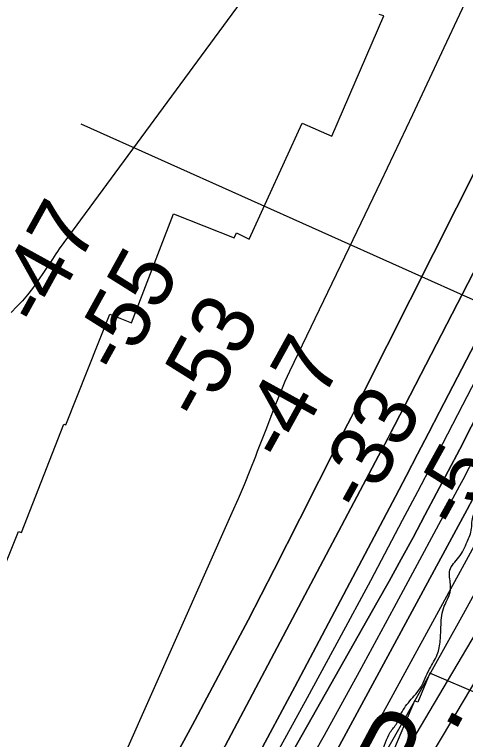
# Model space of a CAD drawing. Extents: x 3297735 to 3335592, y 670436 to 695807.
# Drawn here: x 3321993 to 3322478, y 692965 to 693745 of the extents above; entities that cross this region are included whole.
import ezdxf

# ---------------------------------------------------------------- set-up
doc = ezdxf.new("R2010")
doc.units = 0
for name, color, linetype in [('V-RIVR-EDGE', 7, 'Continuous'), ('V-RIVR-RANG', 7, 'Continuous'), ('V-RRAP-RVMT', 7, 'Continuous'), ('V-TOPO-DPTH', 7, 'Continuous'), ('V-TOPO-MAJR', 7, 'Continuous'), ('V-TOPO-MINR', 7, 'Continuous'), ('V-TOPO-WATR', 7, 'Continuous'), ('V-TOPO-WATR-IDEN', 7, 'Continuous')]:
    doc.layers.add(name, color=color, linetype=linetype)

msp = doc.modelspace()

# ---------------------------------------------------------------- linework, layer by layer
at = {"layer": 'V-RIVR-EDGE'}
msp.add_spline([(3319721.91, 688607.25), (3319733.2, 688627.78), (3319739.82, 688637.46), (3319746.04, 688644.42), (3319750.72, 688655.27), (3319752.28, 688659.14), (3319762.01, 688671.92), (3319781.47, 688699.79), (3319792.76, 688716.44), (3319801.32, 688726.89), (3319810.26, 688738.11), (3319819.98, 688747.01), (3319825.43, 688754.75), (3319830.49, 688762.88), (3319835.55, 688770.63), (3319840.23, 688780.31), (3319844.52, 688791.16), (3319846.86, 688795.42), (3319851.13, 688797.35), (3319854.24, 688799.66), (3319861.24, 688808.95), (3319869.41, 688820.96), (3319874.87, 688831.03), (3319884.99, 688845.35), (3319893.93, 688856.57), (3319900.54, 688860.82), (3319908.31, 688869.72), (3319918.43, 688881.33), (3319923.49, 688889.46), (3319928.16, 688897.21), (3319932.06, 688904.95), (3319939.44, 688912.69), (3319951.5, 688924.3), (3319955, 688930.88), (3319970.57, 688952.17), (3319976.4, 688958.36), (3319980.68, 688966.5), (3319987.3, 688976.95), (3319991.2, 688986.25), (3319997.81, 688992.82), (3320004.81, 689000.56), (3320006.38, 689006.76), (3320010.27, 689012.96), (3320018.06, 689024.96), (3320025.07, 689035.8), (3320031.68, 689044.71), (3320039.46, 689054.38), (3320044.52, 689060.57), (3320057.73, 689071.4), (3320064.34, 689077.2), (3320070.17, 689082.23), (3320074.45, 689090.36), (3320085.73, 689104.68), (3320093.52, 689116.3), (3320109.84, 689130.22), (3320125, 689144.14), (3320145.59, 689159.99), (3320166.96, 689177), (3320184.06, 689191.31), (3320194.55, 689197.87), (3320205.42, 689204.44), (3320211.64, 689209.85), (3320219.42, 689219.53), (3320234.59, 689238.11), (3320241.98, 689244.68), (3320253.64, 689257.45), (3320273.09, 689279.5), (3320283.99, 689297.32), (3320297.61, 689318.61), (3320312.03, 689344.56), (3320320.21, 689360.83), (3320328.41, 689380.97), (3320333.48, 689394.53), (3320349.85, 689425.9), (3320363.1, 689453.41), (3320368.17, 689465.42), (3320370.9, 689469.67), (3320379.06, 689477.41), (3320388.4, 689489.8), (3320394.62, 689499.09), (3320395.41, 689505.29), (3320397.76, 689513.82), (3320403.21, 689520.78), (3320409.04, 689527.75), (3320417.6, 689536.65), (3320423.43, 689544.39), (3320428.49, 689552.52), (3320431.24, 689564.54), (3320432.02, 689568.03), (3320442.14, 689581.19), (3320451.87, 689595.12), (3320462.77, 689612.93), (3320469.38, 689621.06), (3320477.55, 689631.51), (3320493.51, 689653.19), (3320500.9, 689665.19), (3320506.36, 689674.1), (3320514.54, 689688.82), (3320523.5, 689705.47), (3320534.4, 689723.28), (3320539.06, 689727.15), (3320544.9, 689735.28), (3320551.13, 689744.18), (3320556.58, 689752.7), (3320560.87, 689764.32), (3320568.26, 689774), (3320574.5, 689785.23), (3320578.79, 689794.53), (3320583.07, 689802.27), (3320590.86, 689815.83), (3320602.92, 689833.25), (3320613.43, 689849.12), (3320622.79, 689866.94), (3320636.42, 689890.17), (3320646.93, 689907.21), (3320658.22, 689926.96), (3320664.85, 689940.13), (3320664.87, 689948.66), (3320667.22, 689956.02), (3320676.55, 689968.02), (3320685.11, 689978.08), (3320691.73, 689991.25), (3320701.47, 690006.35), (3320706.14, 690016.04), (3320709.66, 690026.11), (3320715.89, 690035.79), (3320728.33, 690049.33), (3320741.18, 690068.69), (3320754.02, 690086.5), (3320761.81, 690100.44), (3320770.77, 690116.32), (3320777.39, 690127.16), (3320786.73, 690139.93), (3320794.89, 690149.22), (3320800.73, 690155.41), (3320806.18, 690166.26), (3320810.47, 690174), (3320820.98, 690192.59), (3320823.74, 690207.71), (3320829.97, 690218.16), (3320840.87, 690235.59), (3320854.1, 690256.5), (3320864.22, 690271.59), (3320869.28, 690277.01), (3320870.45, 690281.27), (3320876.68, 690289.4), (3320887.57, 690302.95), (3320901.57, 690319.98), (3320912.08, 690333.52), (3320919.47, 690342.43), (3320924.52, 690348.23), (3320932.3, 690356.35), (3320941.26, 690371.46), (3320956.44, 690393.91), (3320969.67, 690415.21), (3320973.57, 690422.57), (3320982.13, 690434.96), (3320987.2, 690444.64), (3320994.21, 690457.03), (3321000.83, 690467.87), (3321008.23, 690481.04), (3321017.97, 690500.02), (3321024.59, 690511.64), (3321030.43, 690518.6), (3321035.5, 690530.22), (3321040.94, 690537.19), (3321055.35, 690559.26), (3321068.58, 690577.84), (3321078.31, 690594.1), (3321086.87, 690605.72), (3321095.82, 690616.94), (3321102.82, 690625.84), (3321107.51, 690637.85), (3321113.34, 690645.6), (3321117.63, 690655.67), (3321123.87, 690670), (3321130.5, 690682.39), (3321142.57, 690701.37), (3321156.19, 690722.28), (3321168.65, 690743.19), (3321171.38, 690749.38), (3321176.05, 690754.41), (3321177.22, 690758.29), (3321181.12, 690767.2), (3321185.79, 690774.17), (3321192.03, 690789.28), (3321204.89, 690814.45), (3321214.25, 690834.98), (3321218.93, 690845.83), (3321223.61, 690855.12), (3321229.85, 690869.85), (3321238.03, 690883.79), (3321242.33, 690899.29), (3321247.41, 690912.46), (3321254.43, 690927.96), (3321263, 690946.55), (3321269.64, 690962.82), (3321273.93, 690973.67), (3321278.23, 690986.07), (3321286.44, 691015.52), (3321288.78, 691021.72), (3321293.84, 691028.3), (3321297.35, 691034.5), (3321303.19, 691045.34), (3321306.32, 691054.64), (3321308.29, 691066.66), (3321310.63, 691073.63), (3321314.52, 691079.44), (3321318.04, 691090.29), (3321320.01, 691103.08), (3321324.31, 691115.87), (3321326.26, 691120.13), (3321332.09, 691125.16), (3321336.76, 691133.68), (3321337.17, 691140.65), (3321337.18, 691146.47), (3321338.37, 691158.49), (3321341.12, 691172.44), (3321349.71, 691192.98), (3321372.69, 691236.35), (3321389.06, 691268.5), (3321398.41, 691284.38), (3321404.65, 691298.32), (3321407.38, 691307.24), (3321407.39, 691310.73), (3321407.79, 691316.15), (3321414.41, 691325.06), (3321416.76, 691334.75), (3321417.94, 691344.05), (3321422.24, 691356.06), (3321434.34, 691385.89), (3321448.39, 691422.7), (3321456.19, 691442.46), (3321462.05, 691458.34), (3321462.85, 691466.87), (3321467.91, 691477.72), (3321474.92, 691488.17), (3321481.15, 691497.85), (3321481.54, 691500.57), (3321489.74, 691519.94), (3321499.87, 691542.02), (3321510.79, 691564.87), (3321521.69, 691581.91), (3321529.1, 691598.18), (3321538.84, 691619.09), (3321550.12, 691632.64), (3321559.06, 691640.76), (3321566.84, 691650.44), (3321566.47, 691655.48), (3321567.25, 691659.74), (3321572.7, 691664.77), (3321581.26, 691676.38), (3321584.38, 691684.91), (3321587.11, 691693.43), (3321593.35, 691706.6), (3321601.92, 691721.7), (3321610.87, 691733.32), (3321617.87, 691739.5), (3321620.99, 691748.8), (3321624.5, 691755), (3321632.28, 691766.23), (3321637.34, 691773.97), (3321638.14, 691784.44), (3321641.66, 691795.29), (3321645.96, 691809.63), (3321651.03, 691820.47), (3321653.37, 691824.35), (3321658.42, 691828.99), (3321665.02, 691832.07), (3321673.18, 691838.64), (3321680.2, 691853.75), (3321683.72, 691866.15), (3321687.24, 691878.94), (3321691.93, 691892.5), (3321697.77, 691904.12), (3321704.38, 691909.54), (3321711, 691920.77), (3321724.23, 691939.74), (3321729.68, 691949.8), (3321733.59, 691959.49), (3321746.04, 691978.85), (3321765.1, 692000.13), (3321767.83, 692005.55), (3321769.01, 692012.53), (3321772.52, 692019.89), (3321782.64, 692034.6), (3321793.52, 692045.43), (3321802.86, 692057.43), (3321811.04, 692071.76), (3321820.77, 692085.31), (3321837.5, 692109.31), (3321852.67, 692125.56), (3321856.95, 692134.47), (3321865.51, 692146.08), (3321874.07, 692158.09), (3321882.62, 692162.33), (3321885.73, 692165.42), (3321887.31, 692179.77), (3321889.66, 692189.46), (3321896.67, 692199.14), (3321906.39, 692208.81), (3321914.56, 692218.87), (3321921.95, 692230.87), (3321931.31, 692249.47), (3321940.25, 692259.91), (3321951.52, 692266.48), (3321951.14, 692271.52), (3321953.48, 692276.17), (3321960.48, 692283.13), (3321960.49, 692288.17), (3321960.5, 692292.05), (3321966.73, 692300.96), (3321976.84, 692312.95), (3321985.4, 692326.12), (3321999.02, 692342.37), (3322004.07, 692347.79), (3322006.8, 692355.15), (3322018.86, 692369.86), (3322032.48, 692387.27), (3322035.98, 692394.25), (3322046.88, 692410.89), (3322053.89, 692419.41), (3322062.45, 692431.8), (3322080.36, 692459.29), (3322099.43, 692486.77), (3322109.15, 692500.71), (3322113.45, 692513.5), (3322120.08, 692527.44), (3322124.37, 692536.35), (3322130.59, 692544.09), (3322144.19, 692555.69), (3322154.3, 692563.42), (3322157.8, 692568.07), (3322157.81, 692573.5), (3322158.99, 692580.09), (3322165.23, 692595.2), (3322169.9, 692601), (3322176.9, 692609.9), (3322181.58, 692618.04), (3322185.48, 692627.33), (3322187.82, 692635.08), (3322190.16, 692638.96), (3322199.11, 692652.12), (3322206.11, 692660.24), (3322215.05, 692669.14), (3322221.67, 692679.21), (3322228.68, 692689.66), (3322230.65, 692701.29), (3322234.15, 692707.1), (3322239.98, 692713.68), (3322240.78, 692721.82), (3322246.62, 692732.28), (3322257.13, 692747.76), (3322269.19, 692761.31), (3322281.64, 692779.5), (3322287.08, 692784.53), (3322289.82, 692793.44), (3322298.4, 692811.26), (3322311.23, 692827.9), (3322325.25, 692849.2), (3322340.82, 692872.04), (3322357.55, 692894.49), (3322366.5, 692909.98), (3322374.67, 692919.27), (3322378.18, 692925.85), (3322378.19, 692932.44), (3322378.2, 692936.32), (3322380.16, 692941.75), (3322387.16, 692950.65), (3322397.3, 692972.73), (3322404.3, 692982.41), (3322407.81, 692990.54), (3322418.32, 693006.42), (3322430.38, 693021.51), (3322439.35, 693040.49), (3322447.92, 693056.37), (3322451.06, 693071.49), (3322451.87, 693088.16), (3322455.41, 693108.32), (3322461.66, 693123.43), (3322462.07, 693131.96), (3322461.33, 693147.08), (3322471.06, 693161.02), (3322480.02, 693177.67), (3322484.71, 693192.01), (3322487.85, 693207.9), (3322490.57, 693210.61), (3322500.3, 693224.93), (3322521.3, 693248.15), (3322539.95, 693264), (3322547.34, 693272.91), (3322550.08, 693282.59), (3322550.88, 693291.9), (3322552.45, 693297.71), (3322564.89, 693311.64), (3322570.72, 693318.61), (3322576.95, 693326.74), (3322580.47, 693340.69), (3322590.2, 693351.91), (3322600.3, 693359.25), (3322603.79, 693359.25), (3322609.2, 693353.42), (3322618.52, 693357.27), (3322625.13, 693363.85), (3322634.47, 693378.56), (3322653.93, 693404.88), (3322678.44, 693438.95), (3322692.84, 693458.69), (3322701, 693465.26), (3322708.76, 693467.96), (3322714.21, 693474.54), (3322719.66, 693481.51), (3322729.79, 693501.26), (3322740.68, 693515.19), (3322746.53, 693526.81), (3322752.77, 693541.92), (3322764.43, 693554.69), (3322769.49, 693562.82), (3322774.19, 693578.71), (3322781.2, 693591.1), (3322787.42, 693598.84), (3322795.21, 693610.46), (3322799.12, 693622.47), (3322801.47, 693634.49), (3322804.6, 693643.4), (3322808.49, 693648.82), (3322813.15, 693654.23), (3322817.07, 693670.51), (3322820.98, 693684.08), (3322828, 693699.57), (3322828.79, 693704.61), (3322829.58, 693711.2), (3322831.15, 693715.46), (3322838.93, 693727.85), (3322846.35, 693746.06), (3322854.15, 693763.88), (3322858.81, 693768.14), (3322865.03, 693775.88), (3322871.27, 693789.05), (3322877.11, 693797.95), (3322877.51, 693803.38), (3322881.8, 693810.74), (3322885.32, 693822.75), (3322886.52, 693837.48), (3322887.31, 693846.79), (3322888.49, 693852.22), (3322893.57, 693866.16), (3322903.7, 693885.14), (3322914.59, 693899.85), (3322916.94, 693906.83), (3322916.96, 693914.97), (3322915.81, 693921.56), (3322917, 693934.75), (3322920.53, 693950.25), (3322928.35, 693973.5), (3322938.09, 693991.7), (3322943.16, 694004.1), (3322945.88, 694005.64), (3322947.06, 694014.95), (3322947.71, 694018)], degree=3, dxfattribs=at)
at = {"layer": 'V-RIVR-RANG'}
msp.add_line((3322977.31, 693217.68), (3322065.07, 693627.34), dxfattribs=at)
at = {"layer": 'V-RRAP-RVMT'}
for p, q in [((3322334.6, 693614.16), (3322390.45, 693743.99)), ((3322390.45, 693743.99), (3322385.53, 693745.28)), ((3322245.51, 693503.51), (3322302.48, 693628.41)), ((3322302.48, 693628.41), (3322334.6, 693614.16)), ((3322118.87, 693413.52), (3322164.08, 693530.58)), ((3322164.08, 693530.58), (3322229.43, 693504.94)), ((3322229.43, 693504.94), (3322231.89, 693510.42)), ((3322231.89, 693510.42), (3322245.51, 693503.51)), ((3322048.53, 693303.56), (3322095.63, 693422.78)), ((3322095.63, 693422.78), (3322118.87, 693413.52)), ((3322000.68, 693187.62), (3322046.41, 693304.33)), ((3322046.41, 693304.33), (3322048.53, 693303.56)), ((3321957.14, 693088.74), (3321997.59, 693188.74)), ((3321997.59, 693188.74), (3322000.68, 693187.62)), ((3322439.99, 693036.28), (3322426.91, 693005.28)), ((3322578.4, 692976.91), (3322439.99, 693036.28)), ((3322423.37, 693006.56), (3322377.6, 692898.95)), ((3322426.91, 693005.28), (3322423.37, 693006.56))]:
    msp.add_line(p, q, dxfattribs=at)
at = {"layer": 'V-TOPO-DPTH'}
for points in [[(3321641.43, 692020.95), (3321943.61, 692538.68), (3321957.38, 692562.55), (3321971, 692586.5), (3321984.37, 692610.6), (3321997.59, 692634.78), (3322187.05, 692985.47), (3322215.88, 693039.4), (3322244.39, 693093.5), (3322272.43, 693147.84), (3322300.15, 693202.36), (3322341.34, 693284.26), (3322348.22, 693297.95), (3322355.11, 693311.63), (3322361.99, 693325.31), (3322368.87, 693338.99), (3322493.76, 693587.19), (3322551.49, 693703.06), (3322608.59, 693819.24), (3322664.76, 693935.88), (3322703.65, 694017.76)], [(3322703.65, 694017.76), (3322664.76, 693935.88), (3322608.59, 693819.24), (3322551.49, 693703.06), (3322493.76, 693587.19), (3322368.87, 693338.99), (3322361.99, 693325.31), (3322355.11, 693311.63), (3322348.22, 693297.95), (3322341.34, 693284.26), (3322300.15, 693202.36), (3322272.43, 693147.84), (3322244.39, 693093.5), (3322215.88, 693039.4), (3322187.05, 692985.47), (3321997.59, 692634.78), (3321984.37, 692610.6), (3321971, 692586.5), (3321957.38, 692562.55), (3321943.61, 692538.68), (3321641.43, 692020.95)], [(3321660.22, 691992.11), (3322003.56, 692551.2), (3322004.69, 692553.04), (3322006.95, 692556.73), (3322008.07, 692558.58), (3322010.1, 692561.9), (3322010.53, 692562.64), (3322010.74, 692563.02), (3322013.04, 692567.09), (3322014.39, 692569.51), (3322015.72, 692571.93), (3322017.04, 692574.36), (3322018.34, 692576.8), (3322388.02, 693276.34), (3322391.51, 693282.96), (3322394.99, 693289.59), (3322398.44, 693296.23), (3322401.89, 693302.88), (3322520.3, 693532.2), (3322581.64, 693653.66), (3322641.49, 693775.83), (3322699.12, 693899.06), (3322752.92, 694017.81), (3322809.43, 694017.86)], [(3322703.65, 694017.76), (3322752.92, 694017.81), (3322699.12, 693899.06), (3322641.49, 693775.83), (3322581.64, 693653.66), (3322520.3, 693532.2), (3322401.89, 693302.88), (3322398.44, 693296.23), (3322394.99, 693289.59), (3322391.51, 693282.96), (3322388.02, 693276.34), (3322018.34, 692576.8), (3322017.04, 692574.36), (3322015.72, 692571.93), (3322014.39, 692569.51), (3322013.04, 692567.09), (3322010.74, 692563.02), (3322010.53, 692562.64), (3322010.1, 692561.9), (3322008.07, 692558.58), (3322006.95, 692556.73), (3322004.69, 692553.04), (3322003.56, 692551.2), (3321660.22, 691992.11)], [(3321798.41, 692123.03), (3321832.83, 692178.16), (3321867.33, 692233.23), (3322027.07, 692487.63), (3322041.46, 692510.91), (3322055.63, 692534.31), (3322069.48, 692557.91), (3322083.1, 692581.63), (3322382.83, 693111.91), (3322395.96, 693135.37), (3322408.96, 693158.89), (3322421.76, 693182.53), (3322434.44, 693206.23), (3322446.99, 693230), (3322459.51, 693253.79), (3322471.97, 693277.61), (3322484.4, 693301.44), (3322498.11, 693327.8), (3322517.17, 693364.93), (3322535.99, 693402.17), (3322554.43, 693439.61), (3322572.63, 693477.17), (3322831.18, 694017.89), (3322900.35, 694017.96)], [(3322809.43, 694017.86), (3322831.18, 694017.89), (3322572.63, 693477.17), (3322554.43, 693439.61), (3322535.99, 693402.17), (3322517.17, 693364.93), (3322498.11, 693327.8), (3322484.4, 693301.44), (3322471.97, 693277.61), (3322459.51, 693253.79), (3322446.99, 693230), (3322434.44, 693206.23), (3322421.76, 693182.53), (3322408.96, 693158.89), (3322395.96, 693135.37), (3322382.83, 693111.91), (3322083.1, 692581.63), (3322069.48, 692557.91), (3322055.63, 692534.31), (3322041.46, 692510.91), (3322027.07, 692487.63), (3321867.33, 692233.23), (3321832.83, 692178.16), (3321798.41, 692123.03)], [(3321966.31, 692243.7), (3322005.88, 692305.72), (3322045.35, 692367.8), (3322105.62, 692462.83), (3322114.81, 692477.49), (3322123.89, 692492.21), (3322132.82, 692507.03), (3322141.64, 692521.92), (3322345.87, 692870.83), (3322378.49, 692927.06), (3322410.81, 692983.46), (3322442.67, 693040.11), (3322474.25, 693096.93), (3322499.67, 693143.12), (3322518.23, 693177.01), (3322536.67, 693210.96), (3322554.96, 693245), (3322573.15, 693279.09), (3322608.19, 693345.15), (3322643.46, 693412.5), (3322678.26, 693480.08), (3322712.35, 693548.03), (3322745.97, 693616.22), (3322941.47, 694018)], [(3322900.35, 694017.96), (3322504.56, 693258.89), (3322498.45, 693247.23), (3322492.3, 693235.59), (3322486.1, 693223.98), (3322479.87, 693212.39), (3322136.95, 692577.8), (3322130.58, 692566.13), (3322124.14, 692554.5), (3322117.6, 692542.93), (3322110.99, 692531.4), (3322099.41, 692511.41), (3322097.63, 692508.41), (3322096.72, 692506.93), (3322095.79, 692505.45), (3322089.9, 692496.22), (3322085.98, 692490.16), (3322082.03, 692484.12), (3322078.01, 692478.13), (3322073.96, 692472.16), (3322026.33, 692402.8), (3321998.45, 692362.15), (3321970.6, 692321.49)], [(3322900.35, 694017.96), (3322504.56, 693258.89), (3322498.45, 693247.23), (3322492.3, 693235.59), (3322486.1, 693223.98), (3322479.87, 693212.39), (3322136.95, 692577.8), (3322130.58, 692566.13), (3322124.14, 692554.5), (3322117.6, 692542.93), (3322110.99, 692531.4), (3322099.41, 692511.41), (3322097.63, 692508.41), (3322096.72, 692506.93), (3322095.79, 692505.45), (3322089.9, 692496.22), (3322085.98, 692490.16), (3322082.03, 692484.12), (3322078.01, 692478.13), (3322073.96, 692472.16), (3322026.33, 692402.8), (3321998.45, 692362.15), (3321970.6, 692321.49)], [(3321668.7, 691956.09), (3321827.73, 692215.24), (3321861.87, 692270.79), (3321896.05, 692326.31), (3321930.3, 692381.8), (3321964.6, 692437.25), (3322018.61, 692524.49), (3322025.86, 692536.35), (3322033.01, 692548.27), (3322040.01, 692560.27), (3322046.91, 692572.34), (3322121.84, 692705.17), (3322165.81, 692783.87), (3322209.33, 692862.81), (3322252.2, 692942.11), (3322294.63, 693021.65), (3322402.84, 693226.57), (3322414.79, 693249.27), (3322426.71, 693271.99), (3322438.58, 693294.73), (3322450.41, 693317.5), (3322686.95, 693773.81)], [(3322686.95, 693773.81), (3322450.41, 693317.5), (3322438.58, 693294.73), (3322426.71, 693271.99), (3322414.79, 693249.27), (3322402.84, 693226.57), (3322294.63, 693021.65), (3322252.2, 692942.11), (3322209.33, 692862.81), (3322165.81, 692783.87), (3322121.84, 692705.17), (3322046.91, 692572.34), (3322040.01, 692560.27), (3322033.01, 692548.27), (3322025.86, 692536.35), (3322018.61, 692524.49), (3321964.6, 692437.25), (3321930.3, 692381.8), (3321896.05, 692326.31), (3321861.87, 692270.79), (3321827.73, 692215.24), (3321668.7, 691956.09)]]:
    msp.add_lwpolyline(points, dxfattribs=at)
at = {"layer": 'V-TOPO-MAJR'}
for points in [[(3322426.42, 694017.47), (3322041.14, 693493.16), (3322039.44, 693490.35), (3322037.71, 693487.56), (3322035.94, 693484.8), (3322034.13, 693482.06), (3322017.7, 693457.58), (3322012.67, 693450.53), (3322007.37, 693443.7), (3322001.7, 693437.18), (3321995.76, 693430.87), (3321989.64, 693424.71)], [(3322082.91, 692883.6), (3322227.45, 693209.35), (3322233.99, 693224.4), (3322240.39, 693239.5), (3322246.57, 693254.7), (3322252.6, 693269.96), (3322254.7, 693275.39), (3322259.58, 693287.98), (3322264.47, 693300.56), (3322269.37, 693313.13), (3322274.29, 693325.7), (3322279.87, 693339.93), (3322282.07, 693345.35), (3322284.34, 693350.74), (3322286.74, 693356.07), (3322289.22, 693361.37), (3322353.13, 693494.15), (3322387.48, 693565.88), (3322421.61, 693637.71), (3322455.44, 693709.69), (3322489.07, 693781.76)]]:
    msp.add_lwpolyline(points, dxfattribs=at)
at = {"layer": 'V-TOPO-MINR'}
for points in [[(3322703.65, 694017.76), (3322664.76, 693935.88), (3322608.59, 693819.24), (3322551.49, 693703.06), (3322493.76, 693587.19), (3322368.87, 693338.99), (3322361.99, 693325.31), (3322355.11, 693311.63), (3322348.22, 693297.95), (3322341.34, 693284.26), (3322300.15, 693202.36), (3322272.43, 693147.84), (3322244.39, 693093.5), (3322215.88, 693039.4), (3322187.05, 692985.47), (3321997.59, 692634.78), (3321984.37, 692610.6), (3321971, 692586.5), (3321957.38, 692562.55), (3321943.61, 692538.68), (3321641.43, 692020.95)], [(3321660.22, 691992.11), (3322003.56, 692551.2), (3322004.69, 692553.04), (3322006.95, 692556.73), (3322008.07, 692558.58), (3322010.1, 692561.9), (3322010.53, 692562.64), (3322010.74, 692563.02), (3322013.04, 692567.09), (3322014.39, 692569.51), (3322015.72, 692571.93), (3322017.04, 692574.36), (3322018.34, 692576.8), (3322388.02, 693276.34), (3322391.51, 693282.96), (3322394.99, 693289.59), (3322398.44, 693296.23), (3322401.89, 693302.88), (3322520.3, 693532.2), (3322581.64, 693653.66), (3322641.49, 693775.83), (3322699.12, 693899.06), (3322752.92, 694017.81)], [(3321794.88, 692094.38), (3322032, 692464.39), (3322051.2, 692494.8), (3322070.12, 692525.38), (3322088.61, 692556.22), (3322106.83, 692587.23), (3322249.18, 692833.41), (3322288.05, 692901.36), (3322326.48, 692969.54), (3322364.28, 693038.08), (3322401.64, 693106.87), (3322472.29, 693238.39), (3322474, 693241.59), (3322475.71, 693244.8), (3322477.41, 693248.01), (3322479.1, 693251.23), (3322555.95, 693397.88), (3322595.43, 693474.74), (3322634.06, 693552.01), (3322671.43, 693629.9), (3322707.95, 693708.21), (3322849.31, 694017.9)], [(3321798.41, 692123.03), (3321832.83, 692178.16), (3321867.33, 692233.23), (3322027.07, 692487.63), (3322041.46, 692510.91), (3322055.63, 692534.31), (3322069.48, 692557.91), (3322083.1, 692581.63), (3322382.83, 693111.91), (3322395.96, 693135.37), (3322408.96, 693158.89), (3322421.76, 693182.53), (3322434.44, 693206.23), (3322446.99, 693230), (3322459.51, 693253.79), (3322471.97, 693277.61), (3322484.4, 693301.44), (3322498.11, 693327.8), (3322517.17, 693364.93), (3322535.99, 693402.17), (3322554.43, 693439.61), (3322572.63, 693477.17), (3322831.18, 694017.89)], [(3321905.2, 692115.9), (3321946.44, 692181.18), (3321987.68, 692246.46), (3322110.67, 692441.17), (3322124.03, 692462.53), (3322137.26, 692483.96), (3322150.3, 692505.51), (3322163.21, 692527.14), (3322519.25, 693129.59), (3322525.97, 693141.03), (3322532.66, 693152.49), (3322539.28, 693163.99), (3322545.87, 693175.51), (3322557.75, 693196.43), (3322560.17, 693200.77), (3322668.56, 693400.17), (3322722.31, 693501.48), (3322774.67, 693603.49), (3322824.96, 693706.54), (3322873.85, 693810.29), (3322969.19, 694018.03)], [(3321966.31, 692243.7), (3322005.88, 692305.72), (3322045.35, 692367.8), (3322105.62, 692462.83), (3322114.81, 692477.49), (3322123.89, 692492.21), (3322132.82, 692507.03), (3322141.64, 692521.92), (3322345.87, 692870.83), (3322378.49, 692927.06), (3322410.81, 692983.46), (3322442.67, 693040.11), (3322474.25, 693096.93), (3322499.67, 693143.12), (3322518.23, 693177.01), (3322536.67, 693210.96), (3322554.96, 693245), (3322573.15, 693279.09), (3322608.19, 693345.15), (3322643.46, 693412.5), (3322678.26, 693480.08), (3322712.35, 693548.03), (3322745.97, 693616.22), (3322941.47, 694018)], [(3321733.95, 691933.47), (3321981.05, 692300.22), (3322003.13, 692333.27), (3322025.04, 692366.42), (3322046.7, 692399.75), (3322068.19, 692433.18), (3322100.67, 692484.16), (3322105.74, 692492.22), (3322110.75, 692500.32), (3322115.65, 692508.48), (3322120.49, 692516.68), (3322186.61, 692630.28), (3322224.19, 692695.46), (3322261.4, 692760.85), (3322298.06, 692826.55), (3322334.35, 692892.46), (3322489.87, 693177.7), (3322502.21, 693200.47), (3322514.49, 693223.27), (3322526.67, 693246.13), (3322538.78, 693269.02), (3322729.13, 693630.79), (3322778.57, 693725.9), (3322827.36, 693821.34)], [(3321668.7, 691956.09), (3321827.73, 692215.24), (3321861.87, 692270.79), (3321896.05, 692326.31), (3321930.3, 692381.8), (3321964.6, 692437.25), (3322018.61, 692524.49), (3322025.86, 692536.35), (3322033.01, 692548.27), (3322040.01, 692560.27), (3322046.91, 692572.34), (3322121.84, 692705.17), (3322165.81, 692783.87), (3322209.33, 692862.81), (3322252.2, 692942.11), (3322294.63, 693021.65), (3322402.84, 693226.57), (3322414.79, 693249.27), (3322426.71, 693271.99), (3322438.58, 693294.73), (3322450.41, 693317.5), (3322686.95, 693773.81)], [(3321797.56, 692143.44), (3321846.06, 692221.95), (3321894.71, 692300.37), (3321943.47, 692378.72), (3322022.87, 692506.05), (3322033.68, 692523.62), (3322044.32, 692541.29), (3322054.74, 692559.09), (3322065, 692576.99), (3322238.91, 692884.97), (3322273.86, 692947.46), (3322308.45, 693010.14), (3322342.53, 693073.1), (3322376.26, 693136.25), (3322410.44, 693200.9), (3322426.79, 693231.89), (3322443.08, 693262.9), (3322459.31, 693293.95), (3322475.48, 693325.03), (3322547.19, 693463.14), (3322598.68, 693563.54), (3322649.51, 693664.27), (3322699.33, 693765.51)], [(3321884.42, 692050.63), (3322116.45, 692415.59), (3322134.92, 692444.8), (3322153.3, 692474.08), (3322171.53, 692503.44), (3322189.67, 692532.86), (3322254.24, 692638.19), (3322304.42, 692720.43), (3322354.37, 692802.8), (3322403.98, 692885.38), (3322453.36, 692968.1), (3322567.5, 693160.24), (3322575, 693172.89), (3322582.49, 693185.54), (3322589.96, 693198.2), (3322597.42, 693210.87), (3322835.08, 693615.29)]]:
    msp.add_lwpolyline(points, dxfattribs=at)
at = {"layer": 'V-TOPO-WATR'}
msp.add_lwpolyline([(3321970.6, 692321.49), (3321998.45, 692362.15), (3322026.33, 692402.8), (3322073.96, 692472.16), (3322078.01, 692478.13), (3322082.03, 692484.12), (3322085.98, 692490.16), (3322089.9, 692496.22), (3322095.79, 692505.45), (3322096.72, 692506.93), (3322097.63, 692508.41), (3322099.41, 692511.41), (3322110.99, 692531.4), (3322117.6, 692542.93), (3322124.14, 692554.5), (3322130.58, 692566.13), (3322136.95, 692577.8), (3322479.87, 693212.39), (3322486.1, 693223.98), (3322492.3, 693235.59), (3322498.45, 693247.23), (3322504.56, 693258.89), (3322900.35, 694017.96)], dxfattribs=at)

# ---------------------------------------------------------------- texts
at = {"layer": 'V-RIVR-RANG'}
for s, p in [('-47', (3322023.53, 693405.9)), ('-55', (3322109.32, 693354.39)), ('-53', (3322195.99, 693304.48)), ('-47', (3322285.85, 693260.34)), ('-33', (3322370.11, 693206.05)), ('-5', (3322474.11, 693187.56))]:
    msp.add_text(s, height=67, rotation=61.11531, dxfattribs=at).set_placement(p)
at = {"layer": 'V-TOPO-WATR-IDEN'}
msp.add_text('L.W.R.P.', height=83, rotation=61.98823, dxfattribs=at).set_placement((3322271.28, 692604.78))

doc.saveas('drawing.dxf')
